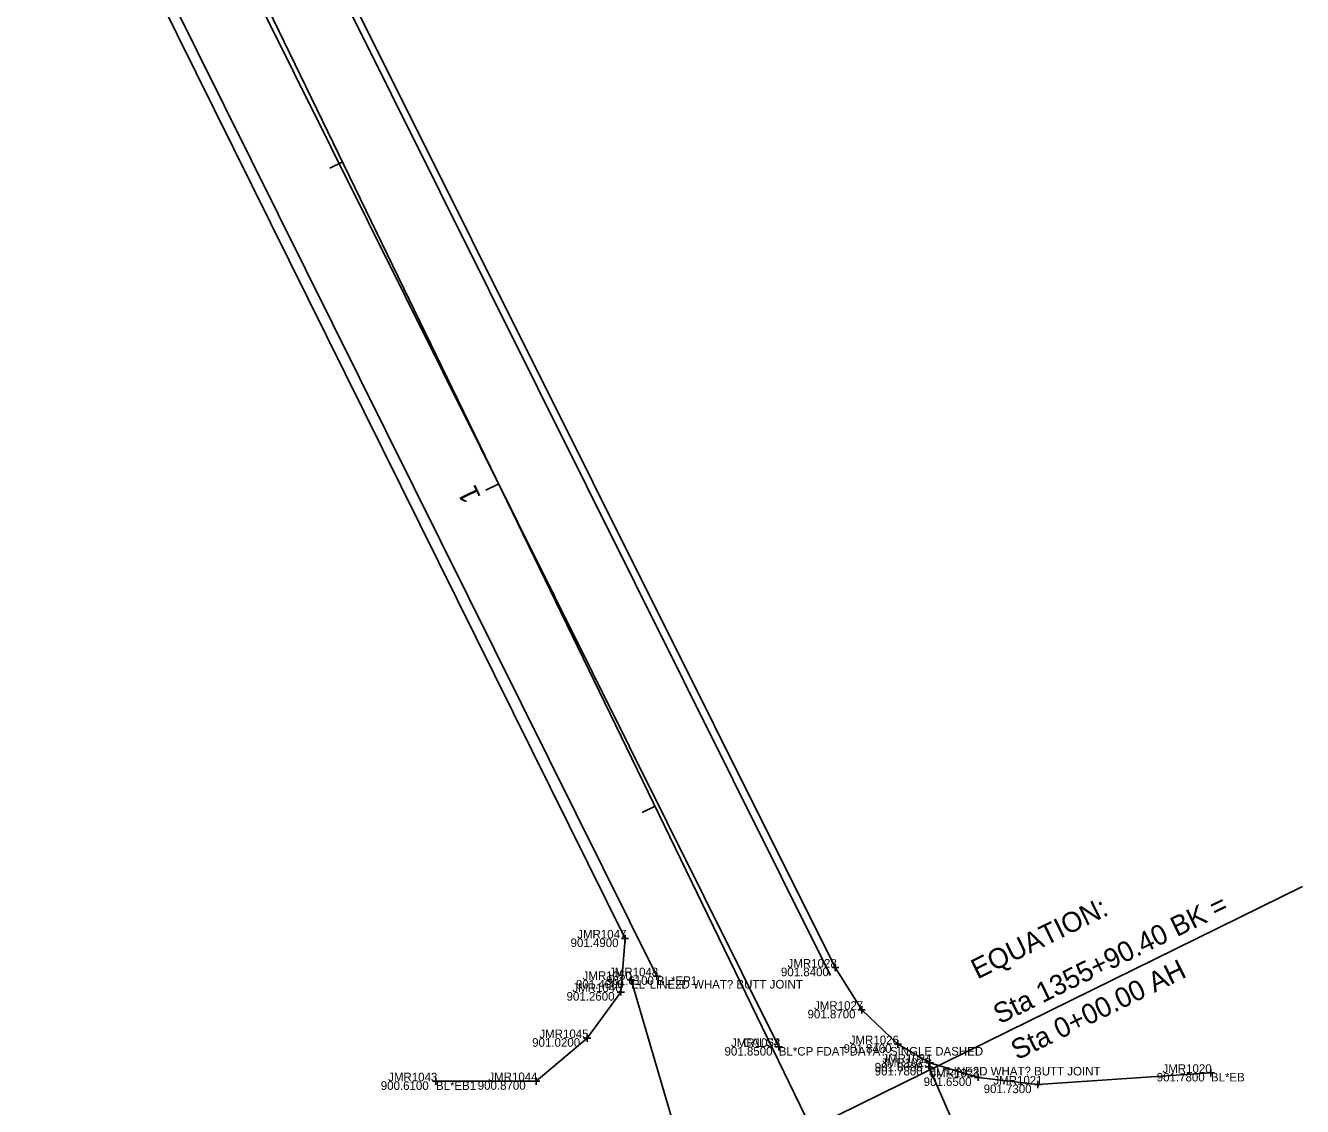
# Model space of a CAD drawing. Extents: x 1800057 to 1804439, y 483822 to 495007.
# Drawn here: x 1804241.5 to 1804419.8, y 483972.7 to 484123.7 of the extents above; entities that cross this region are included whole.
import ezdxf

# ---------------------------------------------------------------- set-up
doc = ezdxf.new("R2010")
doc.units = 0
for name, color, linetype in [('Default', 7, 'Continuous'), ('PV_X_EOP', 7, 'Continuous'), ('PV_X_Shoulder', 7, 'Continuous'), ('SV_X_Center_of_Pavt', 7, 'Continuous'), ('SV_X_CL_Survey_20', 7, 'Continuous'), ('SV_X_Shot_Marker', 7, 'Continuous'), ('SV_X_Text_Comment', 7, 'Continuous'), ('SV_X_Text_Elevation', 7, 'Continuous'), ('SV_X_Text_Name', 7, 'Continuous')]:
    doc.layers.add(name, color=color, linetype=linetype)

msp = doc.modelspace()

# ---------------------------------------------------------------- linework, layer by layer
at = {"layer": 'Default'}
for p, q in [((1804335.76, 483957.63), (1804326.1, 483990.39)), ((1804385.49, 483937.75), (1804367.66, 483978.25))]:
    msp.add_line(p, q, dxfattribs=at)
at = {"layer": 'PV_X_EOP'}
for points in [[(1804329.71, 483990.9), (1804130.26, 484392.39), (1803925.07, 484805.52), (1803733.23, 485192.97), (1803503.17, 485655.24), (1803345.66, 485976.56), (1803141.62, 486388.2), (1802989.93, 486693.23), (1802766.58, 487143.03), (1802634.79, 487407.02), (1802510.61, 487651.27), (1802311.6, 488047.93), (1802029.08, 488615.16), (1801884.85, 488902.81), (1801717.27, 489232.48), (1801690.31, 489285.89), (1801533.42, 489595.91)], [(1804353.88, 483991.09), (1804149.19, 484402.14), (1803944.64, 484814.21), (1803752.3, 485202.72), (1803522.12, 485665.11), (1803364.39, 485986.37), (1803160.55, 486398.05), (1803009.55, 486701.79), (1802785.58, 487152.96), (1802653.73, 487417.2), (1802529.6, 487661.15), (1802332.25, 488055.02), (1802047.67, 488625.21), (1801903.84, 488912.55), (1801733.61, 489247.48)]]:
    msp.add_lwpolyline(points, dxfattribs=at)
at = {"layer": 'PV_X_Shoulder'}
for points in [[(1804298.85, 483976.23), (1804312.84, 483976.26), (1804319.97, 483982.26), (1804324.66, 483988.7), (1804325.26, 483996.18), (1804129.29, 484391.89), (1803924.32, 484805.39), (1803732.65, 485192.61), (1803502.52, 485654.87), (1803344.75, 485976.07), (1803140.78, 486387.9), (1802989.07, 486692.71), (1802765.53, 487142.64), (1802634.07, 487406.54), (1802509.87, 487650.8), (1802310.77, 488047.35), (1802027.8, 488614.53), (1801883.83, 488903.05), (1801716.45, 489232.14), (1801689.68, 489285.36), (1801532.52, 489595.5)], [(1804407.06, 483977.41), (1804382.91, 483975.78), (1804374.54, 483976.78), (1804367.82, 483978.82), (1804363.36, 483981.41), (1804358.3, 483986.22), (1804354.61, 483992.11), (1804149.86, 484402.38), (1803945.5, 484814.74), (1803753.3, 485203.06), (1803523.07, 485665.66), (1803365.32, 485986.68), (1803161.24, 486398.4), (1803010.15, 486702.01)]]:
    msp.add_lwpolyline(points, dxfattribs=at)
at = {"layer": 'SV_X_Center_of_Pavt'}
msp.add_lwpolyline([(1804346.72, 483981.03), (1804139.63, 484397.22), (1803934.15, 484809.54), (1803743.02, 485197.76), (1803512.75, 485659.58), (1803355.16, 485981.5), (1803150.68, 486393.24), (1803000.16, 486697.55), (1802775.94, 487148.36), (1802645.02, 487411.5), (1802520.06, 487655.91), (1802321.93, 488051.2), (1802037.72, 488620.74), (1801894.32, 488907.73), (1801721.3, 489247.63)], dxfattribs=at)
at = {"layer": 'SV_X_CL_Survey_20'}
for p, q in [((1804351.25, 483969.67), (1804113.2, 484460.86)), ((1804285.83, 484104.65), (1804284.03, 484103.78)), ((1804307.64, 484059.66), (1804305.84, 484058.79)), ((1804329.44, 484014.67), (1804327.64, 484013.79)), ((1804352.15, 483970.11), (1804419.84, 484003.42))]:
    msp.add_line(p, q, dxfattribs=at)
at = {"layer": 'SV_X_Shot_Marker'}
for p, q in [((1804325.26, 483996.68), (1804325.26, 483995.68)), ((1804324.76, 483996.18), (1804325.76, 483996.18)), ((1804325.26, 483996.18), (1804325.26, 483996.18)), ((1804329.71, 483991.4), (1804329.71, 483990.4)), ((1804353.85, 483991.09), (1804353.9, 483991.09)), ((1804353.88, 483991.11), (1804353.88, 483991.07)), ((1804353.88, 483991.09), (1804353.88, 483991.09)), ((1804354.11, 483992.11), (1804355.11, 483992.11)), ((1804354.61, 483992.61), (1804354.61, 483991.61)), ((1804354.61, 483992.11), (1804354.61, 483992.11)), ((1804325.6, 483990.39), (1804326.6, 483990.39)), ((1804326.1, 483990.89), (1804326.1, 483989.89)), ((1804326.1, 483990.39), (1804326.1, 483990.39)), ((1804329.21, 483990.9), (1804330.21, 483990.9)), ((1804329.71, 483990.9), (1804329.71, 483990.9)), ((1804324.16, 483988.7), (1804325.16, 483988.7)), ((1804324.66, 483989.2), (1804324.66, 483988.2)), ((1804324.66, 483988.7), (1804324.66, 483988.7)), ((1804357.8, 483986.22), (1804358.8, 483986.22)), ((1804358.3, 483986.72), (1804358.3, 483985.72)), ((1804358.3, 483986.22), (1804358.3, 483986.22)), ((1804319.47, 483982.26), (1804320.47, 483982.26)), ((1804319.97, 483982.76), (1804319.97, 483981.76)), ((1804319.97, 483982.26), (1804319.97, 483982.26)), ((1804346.22, 483981.03), (1804347.22, 483981.03)), ((1804346.22, 483981.03), (1804347.22, 483981.03)), ((1804346.72, 483981.53), (1804346.72, 483980.53)), ((1804346.72, 483981.53), (1804346.72, 483980.53)), ((1804346.72, 483981.03), (1804346.72, 483981.03)), ((1804346.72, 483981.03), (1804346.72, 483981.03)), ((1804362.86, 483981.41), (1804363.86, 483981.41)), ((1804363.36, 483981.91), (1804363.36, 483980.91)), ((1804363.36, 483981.41), (1804363.36, 483981.41)), ((1804367.32, 483978.82), (1804368.32, 483978.82)), ((1804367.66, 483978.75), (1804367.66, 483977.75)), ((1804367.82, 483979.32), (1804367.82, 483978.32)), ((1804367.82, 483978.82), (1804367.82, 483978.82)), ((1804312.84, 483976.76), (1804312.84, 483975.76)), ((1804367.16, 483978.25), (1804368.16, 483978.25)), ((1804367.66, 483978.25), (1804367.66, 483978.25)), ((1804374.04, 483976.78), (1804375.04, 483976.78)), ((1804374.54, 483977.28), (1804374.54, 483976.28)), ((1804374.54, 483976.78), (1804374.54, 483976.78)), ((1804406.56, 483977.41), (1804407.56, 483977.41)), ((1804407.06, 483977.91), (1804407.06, 483976.91)), ((1804407.06, 483977.41), (1804407.06, 483977.41)), ((1804298.35, 483976.23), (1804299.35, 483976.23)), ((1804298.85, 483976.73), (1804298.85, 483975.73)), ((1804298.85, 483976.23), (1804298.85, 483976.23)), ((1804312.34, 483976.26), (1804313.34, 483976.26)), ((1804312.84, 483976.26), (1804312.84, 483976.26)), ((1804382.41, 483975.78), (1804383.41, 483975.78)), ((1804382.91, 483976.28), (1804382.91, 483975.28)), ((1804382.91, 483975.78), (1804382.91, 483975.78))]:
    msp.add_line(p, q, dxfattribs=at)

# ---------------------------------------------------------------- texts
at = {"layer": 'SV_X_CL_Survey_20'}
for s, rotation, p in [('1', 115.8566, (1804305.19, 484057.83)), ('EQUATION:', 26.1993, (1804374.46, 483990.45)), ('Sta 1355+90.40 BK = ', 26.1993, (1804377.55, 483984.17)), ('Sta 0+00.00 AH', 26.1993, (1804380.02, 483979.15))]:
    msp.add_text(s, height=2.8, rotation=rotation, dxfattribs=at).set_placement(p)
at = {"layer": 'SV_X_Text_Comment'}
for s, height, p in [('BL*EP', 0.06, (1804353.88, 483991.03)), ('EL*LINE2D WHAT? BUTT JOINT', 1.2, (1804326.1, 483989.19)), ('BL*EP1', 1.2, (1804329.71, 483989.7)), ('BL*CP FDAT DATA? SINGLE DASHED', 1.2, (1804346.72, 483979.83)), ('EL*LINE2D WHAT? BUTT JOINT', 1.2, (1804367.66, 483977.05)), ('BL*EB', 1.2, (1804407.06, 483976.21)), ('BL*EB1', 1.2, (1804298.85, 483975.03))]:
    msp.add_text(s, height=height, dxfattribs=at).set_placement(p)
at = {"layer": 'SV_X_Text_Elevation'}
for s, height, p in [('901.4900', 1.2, (1804317.65, 483994.98)), ('901.8400', 1.2, (1804347.02, 483990.91)), ('901.7800', 0.06, (1804353.5, 483991.03)), ('901.4000', 1.2, (1804318.4, 483989.19)), ('901.6100', 1.2, (1804322.59, 483989.7)), ('901.2600', 1.2, (1804317.09, 483987.5)), ('901.8700', 1.2, (1804350.74, 483985.02)), ('901.0200', 1.2, (1804312.29, 483981.06)), ('901.8500', 1.2, (1804339.15, 483979.83)), ('901.8500', 1.2, (1804339.15, 483979.83)), ('901.8400', 1.2, (1804355.78, 483980.21)), ('901.8000', 1.2, (1804360.13, 483977.62)), ('901.7800', 1.2, (1804360.11, 483977.05)), ('901.6500', 1.2, (1804366.95, 483975.58)), ('901.7800', 1.2, (1804399.5, 483976.21)), ('900.6100', 1.2, (1804291.15, 483975.03)), ('900.8700', 1.2, (1804304.69, 483975.05)), ('901.7300', 1.2, (1804375.33, 483974.58))]:
    msp.add_text(s, height=height, dxfattribs=at).set_placement(p)
at = {"layer": 'SV_X_Text_Name'}
for s, height, p in [('JMR1047', 1.2, (1804318.58, 483996.18)), ('JMR1028', 1.2, (1804347.95, 483992.11)), ('JMR1050', 1.2, (1804319.33, 483990.39)), ('JMR1048', 1.2, (1804323.02, 483990.9)), ('JMR1029', 0.06, (1804353.54, 483991.09)), ('JMR1046', 1.2, (1804317.91, 483988.7)), ('JMR1027', 1.2, (1804351.65, 483986.22)), ('JMR1045', 1.2, (1804313.29, 483982.26)), ('JMR1052', 1.2, (1804340.06, 483981.03)), ('CALC4', 1.2, (1804341.74, 483981.03)), ('JMR1026', 1.2, (1804356.63, 483981.41)), ('JMR1025', 1.2, (1804361.01, 483978.25)), ('JMR1024', 1.2, (1804361.18, 483978.82)), ('JMR1020', 1.2, (1804400.3, 483977.41)), ('JMR1043', 1.2, (1804292.18, 483976.23)), ('JMR1044', 1.2, (1804306.17, 483976.26)), ('JMR1023', 1.2, (1804367.89, 483976.78)), ('JMR1021', 1.2, (1804376.69, 483975.78))]:
    msp.add_text(s, height=height, dxfattribs=at).set_placement(p)

doc.saveas('drawing.dxf')
